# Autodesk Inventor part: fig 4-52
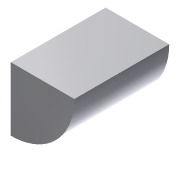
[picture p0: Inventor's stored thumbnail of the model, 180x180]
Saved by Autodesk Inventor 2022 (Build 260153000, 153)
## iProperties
Created: 2010-02
Part Number: fig 4-52
Document SubType Name: Modeling
Designer: CADSoft
Density: 1 g/cm^3
Material: Generic
Appearance: Default
Author: CADSoft
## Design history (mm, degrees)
sketch "Sketch1"
  geometry: L1 (0, 30.039)-(20.155, 30.039); L2 (20.155, 30.039)-(20.155, 0); L3 (20.155, 0)-(0, 0); L4 (0, 31.977)-(0, -5.62); 1 further point
  constraints: 8 end point, 2 point on line
revolve "Revolution1" sketch "Sketch1" stored, may be unused: angle "d0" = 90 deg
body "Solid1"
